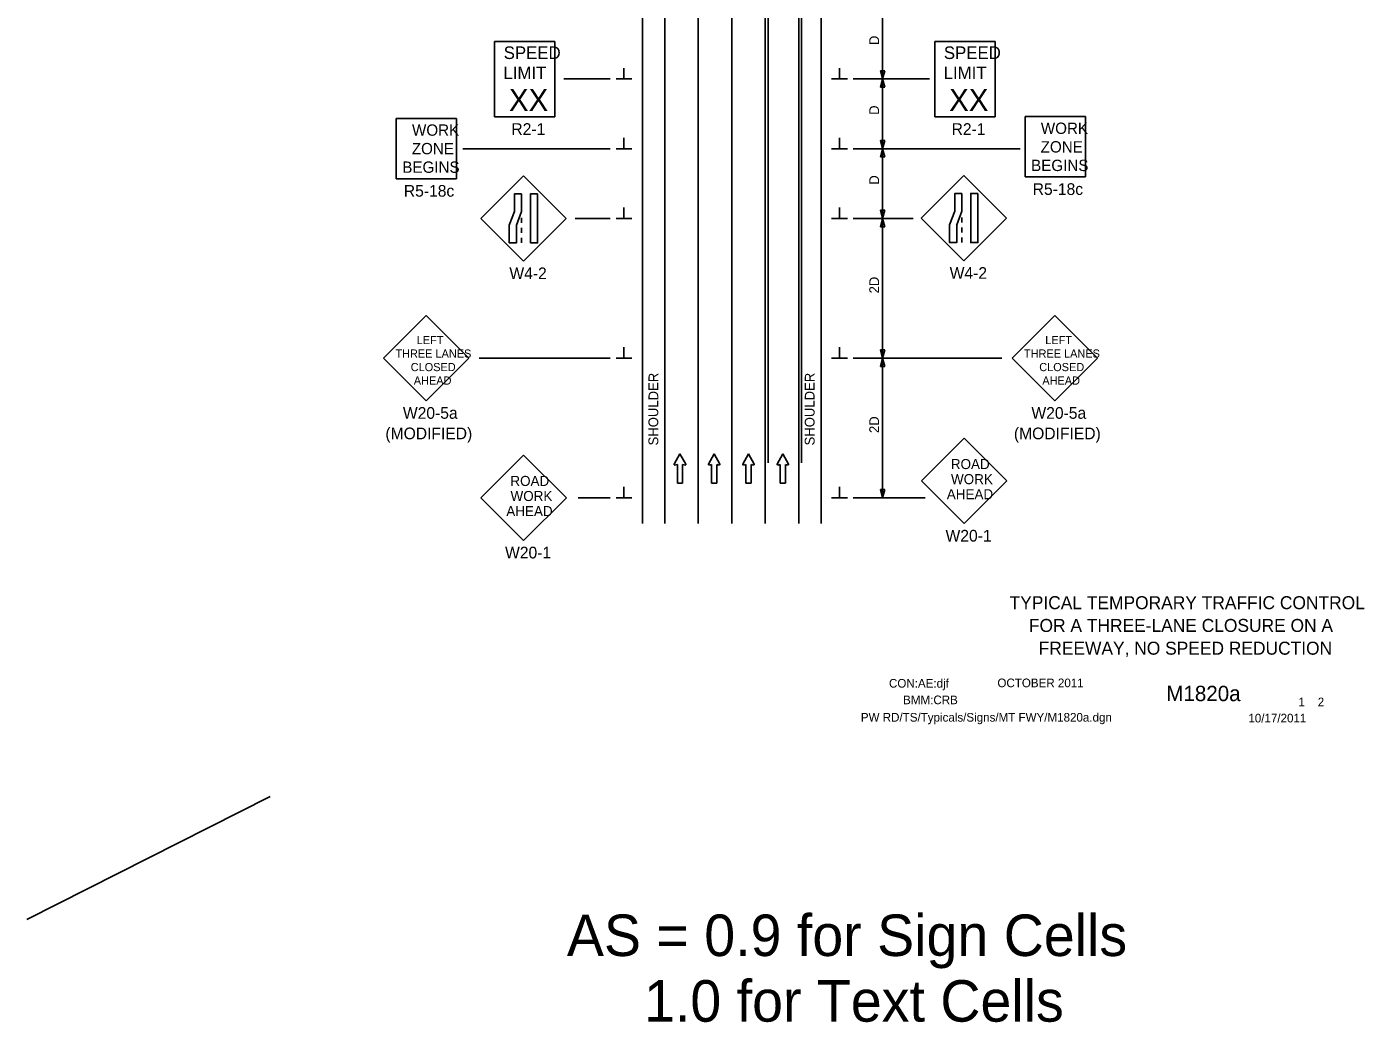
# Model space of a CAD drawing. Extents: x 16473 to 18475, y 7005 to 8296.
# Drawn here: x 16473 to 17431, y 7005 to 7718 of the extents above; entities that cross this region are included whole.
import ezdxf

# ---------------------------------------------------------------- set-up
doc = ezdxf.new("R2010")
doc.units = 0
for name, color, linetype in [('ALI_LEGAL_EX', 7, 'Continuous'), ('BORDER', 7, 'Continuous'), ('BORDER_SIGNAL_WO', 7, 'Continuous'), ('MT_SCRATCH_LEVEL_E', 7, 'Continuous'), ('PAVT_EDGE_EX', 7, 'Continuous'), ('TRAFFIC_SIGNS_PR', 7, 'Continuous'), ('TYPICAL_TEXT_DIMEN_PR', 7, 'Continuous')]:
    doc.layers.add(name, color=color, linetype=linetype)

msp = doc.modelspace()

# ---------------------------------------------------------------- linework, layer by layer
at = {"layer": 'ALI_LEGAL_EX'}
for p, q in [((16954.13, 7361.76), (16954.13, 8295.71)), ((16978.13, 7361.76), (16978.13, 8295.71)), ((17002.13, 7361.76), (17002.13, 8295.71)), ((17004.11, 8234.45), (17004.11, 7405.27)), ((17028.11, 8234.45), (17028.11, 7405.27)), ((17028.11, 8234.45), (17028.11, 7405.27))]:
    msp.add_line(p, q, dxfattribs=at)
for points in [[(16954.13, 7661.76), (16954.13, 7686.76)], [(16978.13, 7661.76), (16978.13, 7686.76)], [(17002.13, 7661.76), (17002.13, 7686.76)], [(16954.13, 7561.76), (16954.13, 7586.76)], [(16978.13, 7561.76), (16978.13, 7586.76)], [(17002.13, 7561.76), (17002.13, 7586.76)], [(16954.13, 7461.76), (16954.13, 7486.76)], [(16978.13, 7486.76), (16978.13, 7461.76)], [(16978.13, 7486.76), (16978.13, 7461.76)], [(17002.13, 7461.76), (17002.13, 7486.76)], [(16954.13, 7361.76), (16954.13, 7386.76)], [(16978.13, 7361.76), (16978.13, 7386.76)], [(17002.13, 7361.76), (17002.13, 7386.76)]]:
    msp.add_lwpolyline(points, dxfattribs=at)
at = {"layer": 'MT_SCRATCH_LEVEL_E'}
for p, q in [((16941.04, 7411.65), (16936.93, 7404.41)), ((16945.18, 7404.41), (16941.04, 7411.65)), ((16965.57, 7411.65), (16961.46, 7404.41)), ((16969.71, 7404.41), (16965.57, 7411.65)), ((16990.1, 7411.65), (16985.98, 7404.41)), ((16994.24, 7404.41), (16990.1, 7411.65)), ((17014.65, 7411.65), (17010.54, 7404.41)), ((17018.8, 7404.41), (17014.65, 7411.65)), ((16937.41, 7403.73), (16939.19, 7404.04)), ((16939.19, 7404.04), (16939.19, 7390.79)), ((16942.93, 7390.79), (16942.93, 7404.04)), ((16942.93, 7404.04), (16944.7, 7403.73)), ((16961.94, 7403.73), (16963.71, 7404.04)), ((16963.71, 7404.04), (16963.71, 7390.79)), ((16967.46, 7390.79), (16967.46, 7404.04)), ((16967.46, 7404.04), (16969.23, 7403.73)), ((16986.47, 7403.73), (16988.24, 7404.04)), ((16988.24, 7404.04), (16988.24, 7390.79)), ((16991.99, 7390.79), (16991.99, 7404.04)), ((16991.99, 7404.04), (16993.76, 7403.73)), ((17011.03, 7403.73), (17012.8, 7404.04)), ((17012.8, 7404.04), (17012.8, 7390.79)), ((17016.54, 7390.79), (17016.54, 7404.04)), ((17016.54, 7404.04), (17018.32, 7403.73)), ((16939.19, 7390.79), (16942.93, 7390.79)), ((16963.71, 7390.79), (16967.46, 7390.79)), ((16988.24, 7390.79), (16991.99, 7390.79)), ((17012.8, 7390.79), (17016.54, 7390.79))]:
    msp.add_line(p, q, dxfattribs=at)
for centre, start, end in [((16937.33, 7404.19), 150.42484, 279.96381), ((16944.77, 7404.19), 260.03619, 29.77312), ((16961.86, 7404.19), 150.42484, 279.96381), ((16969.3, 7404.19), 260.03619, 29.77312), ((16986.39, 7404.19), 150.42484, 279.96381), ((16993.83, 7404.19), 260.03619, 29.77312), ((17010.95, 7404.19), 150.42484, 279.96381), ((17018.39, 7404.19), 260.03619, 29.77312)]:
    msp.add_arc(centre, 0.463, start, end, dxfattribs=at)
at = {"layer": 'PAVT_EDGE_EX'}
for p, q in [((16914.13, 8215.4), (16914.13, 7361.76)), ((16930.13, 8215.4), (16930.13, 7361.76)), ((17026.13, 8215.4), (17026.13, 7361.76)), ((17042.13, 8215.4), (17042.13, 7361.76))]:
    msp.add_line(p, q, dxfattribs=at)
at = {"layer": 'TRAFFIC_SIGNS_PR'}
for p, q in [((16808.39, 7707.01), (16851.59, 7707.01)), ((16808.39, 7653.01), (16808.39, 7707.01)), ((16851.59, 7653.01), (16851.59, 7707.01)), ((17123.48, 7707.01), (17166.68, 7707.01)), ((17123.48, 7653.01), (17123.48, 7707.01)), ((17166.68, 7653.01), (17166.68, 7707.01)), ((16738.02, 7608.75), (16738.02, 7651.95)), ((16738.02, 7651.95), (16781.22, 7651.95)), ((16781.22, 7608.75), (16781.22, 7651.95)), ((16808.39, 7653.01), (16851.59, 7653.01)), ((17123.48, 7653.01), (17166.68, 7653.01)), ((17188.14, 7610.02), (17188.14, 7653.22)), ((17188.14, 7653.22), (17231.34, 7653.22)), ((17231.34, 7610.02), (17231.34, 7653.22)), ((16738.02, 7608.75), (16781.22, 7608.75)), ((16829.14, 7610.78), (16798.6, 7580.24)), ((16859.69, 7580.24), (16829.14, 7610.78)), ((17144.3, 7611.03), (17113.75, 7580.48)), ((17174.85, 7580.48), (17144.3, 7611.03)), ((17188.14, 7610.02), (17231.34, 7610.02)), ((16798.6, 7580.24), (16829.14, 7549.69)), ((16827.74, 7580.79), (16827.74, 7577.19)), ((16827.74, 7573.59), (16827.74, 7569.99)), ((16829.14, 7549.69), (16859.69, 7580.24)), ((17113.75, 7580.48), (17144.3, 7549.93)), ((17142.9, 7581.03), (17142.9, 7577.43)), ((17142.9, 7573.83), (17142.9, 7570.23)), ((17144.3, 7549.93), (17174.85, 7580.48)), ((16827.74, 7566.39), (16827.74, 7562.79)), ((17142.9, 7566.63), (17142.9, 7563.03)), ((16759.46, 7510.8), (16728.92, 7480.26)), ((16790.01, 7480.26), (16759.46, 7510.8)), ((17209.36, 7510.8), (17178.81, 7480.26)), ((17239.91, 7480.26), (17209.36, 7510.8)), ((16728.92, 7480.26), (16759.46, 7449.71)), ((16759.46, 7449.71), (16790.01, 7480.26)), ((17178.81, 7480.26), (17209.36, 7449.71)), ((17209.36, 7449.71), (17239.91, 7480.26)), ((17144.48, 7422.88), (17113.93, 7392.33)), ((17175.02, 7392.33), (17144.48, 7422.88)), ((16829.18, 7410.8), (16798.64, 7380.26)), ((16859.73, 7380.26), (16829.18, 7410.8)), ((17113.93, 7392.33), (17144.48, 7361.79)), ((17144.48, 7361.79), (17175.02, 7392.33)), ((16798.64, 7380.26), (16829.18, 7349.71)), ((16829.18, 7349.71), (16859.73, 7380.26))]:
    msp.add_line(p, q, dxfattribs=at)
for points in [[(16827.74, 7597.94), (16827.74, 7585.36), (16823.98, 7575.37), (16823.98, 7562.79), (16818.92, 7562.79), (16818.92, 7575.37), (16822.68, 7585.36), (16822.68, 7597.94)], [(16839.14, 7597.94), (16839.14, 7562.79), (16834.09, 7562.79), (16834.09, 7597.94)], [(17142.9, 7598.18), (17142.9, 7585.6), (17139.13, 7575.61), (17139.13, 7563.03), (17134.08, 7563.03), (17134.08, 7575.61), (17137.84, 7585.6), (17137.84, 7598.18)], [(17154.3, 7598.18), (17154.3, 7563.03), (17149.24, 7563.03), (17149.24, 7598.18)]]:
    msp.add_lwpolyline(points, close=True, dxfattribs=at)
at = {"layer": 'TYPICAL_TEXT_DIMEN_PR'}
for p, q in [((17086.13, 7730.26), (17086.13, 7680.26)), ((16901, 7680.26), (16901, 7688.04)), ((17055.25, 7680.26), (17055.25, 7688.04)), ((16891.13, 7680.26), (16857.85, 7680.26)), ((16895.38, 7680.26), (16906.63, 7680.26)), ((17060.88, 7680.26), (17049.63, 7680.26)), ((17065.13, 7680.26), (17119.76, 7680.26)), ((17086.13, 7680.26), (17084.56, 7686.12)), ((17084.56, 7686.12), (17086.13, 7686.12)), ((17084.56, 7674.39), (17086.13, 7680.26)), ((17084.56, 7674.39), (17086.13, 7680.26)), ((17086.13, 7686.12), (17087.7, 7686.12)), ((17087.7, 7686.12), (17086.13, 7680.26)), ((17086.13, 7680.26), (17087.7, 7674.39)), ((17086.13, 7680.26), (17086.13, 7630.26)), ((17086.13, 7680.26), (17087.7, 7674.39)), ((17086.13, 7674.39), (17084.56, 7674.39)), ((17086.13, 7674.39), (17084.56, 7674.39)), ((17087.7, 7674.39), (17086.13, 7674.39)), ((17087.7, 7674.39), (17086.13, 7674.39)), ((16901, 7630.26), (16901, 7638.04)), ((17055.25, 7630.26), (17055.25, 7638.04)), ((17086.13, 7630.26), (17084.56, 7636.12)), ((17084.56, 7636.12), (17086.13, 7636.12)), ((17086.13, 7636.12), (17087.7, 7636.12)), ((17087.7, 7636.12), (17086.13, 7630.26)), ((16891.13, 7630.26), (16785.65, 7630.26)), ((16895.38, 7630.26), (16906.63, 7630.26)), ((17060.88, 7630.26), (17049.63, 7630.26)), ((17065.13, 7630.26), (17184.56, 7630.26)), ((17084.56, 7624.39), (17086.13, 7630.26)), ((17086.13, 7624.39), (17084.56, 7624.39)), ((17086.13, 7630.26), (17087.7, 7624.39)), ((17086.13, 7630.26), (17086.13, 7580.26)), ((17087.7, 7624.39), (17086.13, 7624.39)), ((16901, 7580.26), (16901, 7588.04)), ((17055.25, 7580.26), (17055.25, 7588.04)), ((17086.13, 7580.26), (17084.56, 7586.12)), ((17084.56, 7586.12), (17086.13, 7586.12)), ((17086.13, 7586.12), (17087.7, 7586.12)), ((17087.7, 7586.12), (17086.13, 7580.26)), ((16891.13, 7580.26), (16866.15, 7580.26)), ((16895.38, 7580.26), (16906.63, 7580.26)), ((17060.88, 7580.26), (17049.63, 7580.26)), ((17065.13, 7580.26), (17108.05, 7580.26)), ((17084.56, 7574.39), (17086.13, 7580.26)), ((17086.13, 7574.39), (17084.56, 7574.39)), ((17086.13, 7580.26), (17086.13, 7480.26)), ((17086.13, 7580.26), (17087.7, 7574.39)), ((17087.7, 7574.39), (17086.13, 7574.39)), ((16901, 7480.26), (16901, 7488.04)), ((17055.25, 7480.26), (17055.25, 7488.04)), ((16891.13, 7480.26), (16797.45, 7480.26)), ((16895.38, 7480.26), (16906.63, 7480.26)), ((17060.88, 7480.26), (17049.63, 7480.26)), ((17065.13, 7480.26), (17171.53, 7480.26)), ((17086.13, 7480.26), (17084.56, 7486.12)), ((17084.56, 7486.12), (17086.13, 7486.12)), ((17084.56, 7474.39), (17086.13, 7480.26)), ((17086.13, 7486.12), (17087.7, 7486.12)), ((17087.7, 7486.12), (17086.13, 7480.26)), ((17086.13, 7480.26), (17086.13, 7380.26)), ((17086.13, 7480.26), (17087.7, 7474.39)), ((17086.13, 7474.39), (17084.56, 7474.39)), ((17087.7, 7474.39), (17086.13, 7474.39)), ((16901, 7380.26), (16901, 7388.04)), ((17055.25, 7380.26), (17055.25, 7388.04)), ((17086.13, 7380.26), (17084.56, 7386.12)), ((17084.56, 7386.12), (17086.13, 7386.12)), ((17086.13, 7386.12), (17087.7, 7386.12)), ((17087.7, 7386.12), (17086.13, 7380.26)), ((16891.13, 7380.26), (16868.28, 7380.26)), ((16895.38, 7380.26), (16906.63, 7380.26)), ((17060.88, 7380.26), (17049.63, 7380.26)), ((17065.13, 7380.26), (17116.58, 7380.26)), ((16647.75, 7166.25), (16473.49, 7078.33))]:
    msp.add_line(p, q, dxfattribs=at)

# ---------------------------------------------------------------- texts
at = {"layer": 'BORDER'}
for s, p in [('TYPICAL TEMPORARY TRAFFIC CONTROL', (17177.02, 7300.49)), ('FOR A THREE-LANE CLOSURE ON A', (17190.84, 7284.19)), ('FREEWAY, NO SPEED REDUCTION', (17197.83, 7267.89))]:
    msp.add_text(s, height=9.3, dxfattribs=at).set_placement(p)
at = {"layer": 'BORDER_SIGNAL_WO'}
for s, height, p in [('CON:AE:djf  ', 6.2, (17090.69, 7244.31)), ('    OCTOBER 2011', 6.2, (17159.08, 7244.59)), ('BMM:CRB', 6.2, (17100.81, 7232.42)), ('    M1820a   ', 11, (17272.86, 7234.63)), (' 1    2 ', 6.2, (17381.45, 7230.95)), ('PW RD/TS/Typicals/Signs/MT FWY/M1820a.dgn      ', 6.2, (17070.55, 7219.96)), ('10/17/2011', 6.2, (17347.93, 7219.38)), ('AS = 0.9 for Sign Cells', 29.7271, (16860.13, 7052.09)), ('     1.0 for Text Cells', 29.7271, (16860.13, 7005.09))]:
    msp.add_text(s, height=height, dxfattribs=at).set_placement(p)
at = {"layer": 'TRAFFIC_SIGNS_PR'}
for s, height, p in [('SPEED', 9, (16814.88, 7694.48)), ('SPEED', 9, (17129.96, 7694.48)), ('LIMIT', 9, (16814.69, 7680.08)), ('LIMIT', 9, (17129.78, 7680.08)), ('XX', 15.785, (16818.64, 7657.24)), ('XX', 15.785, (17133.73, 7657.24)), ('WORK', 8.119, (16749.27, 7639.54)), ('R2-1', 8.37, (16820.4, 7640.14)), ('R2-1', 8.37, (17135.49, 7640.14)), ('WORK', 8.119, (17199.39, 7640.81)), ('ZONE', 8.119, (16749.13, 7626.25)), ('ZONE', 8.119, (17199.26, 7627.52)), ('BEGINS', 8.119, (16742.3, 7612.97)), ('BEGINS', 8.119, (17192.42, 7614.24)), ('R5-18c', 8.37, (16743.43, 7595.88)), ('R5-18c', 8.37, (17193.55, 7597.15)), ('W4-2', 8.37, (16818.97, 7536.82)), ('W4-2', 8.37, (17134.13, 7537.06)), ('LEFT', 5.85, (16752.65, 7490.31)), ('LEFT', 5.85, (17202.55, 7490.31)), ('THREE LANES', 5.85, (16737.4, 7480.63)), ('THREE LANES', 5.85, (17187.3, 7480.63)), ('CLOSED', 5.85, (16748.35, 7470.95)), ('CLOSED', 5.85, (17198.25, 7470.95)), ('AHEAD', 5.85, (16750.54, 7461.28)), ('AHEAD', 5.85, (17200.44, 7461.28)), ('W20-5a', 8.37, (16742.75, 7436.84)), ('W20-5a', 8.37, (17192.64, 7436.84)), ('(MODIFIED)', 8.37, (16730.21, 7422.17)), ('(MODIFIED)', 8.37, (17180.1, 7422.17)), ('ROAD', 7.2, (17134.96, 7400.81)), ('ROAD', 7.2, (16819.67, 7388.73)), ('WORK', 7.2, (17135.08, 7390.01)), ('WORK', 7.2, (16819.79, 7377.93)), ('AHEAD', 7.2, (17132.06, 7379.21)), ('AHEAD', 7.2, (16816.76, 7367.13)), ('W20-1', 8.37, (17131.17, 7348.92)), ('W20-1', 8.37, (16815.87, 7336.84))]:
    msp.add_text(s, height=height, dxfattribs=at).set_placement(p)
at = {"layer": 'TYPICAL_TEXT_DIMEN_PR'}
for s, p in [('D', (17083.57, 7704.47)), ('D', (17083.57, 7654.47)), ('D', (17083.57, 7604.47)), ('2D', (17083.57, 7526.62)), ('SHOULDER', (16925.51, 7417.76)), ('SHOULDER', (17037.41, 7417.76)), ('2D', (17083.57, 7426.62))]:
    msp.add_text(s, height=7, rotation=90, dxfattribs=at).set_placement(p)

doc.saveas('drawing.dxf')
